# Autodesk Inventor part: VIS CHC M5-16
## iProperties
Created: 2004-11
Part Number: VIS CHC M5-16
Document SubType Name: Modeling
Designer: Bruno
Manufacturer: Standard
Standards Organization: Custom
Author: Bruno
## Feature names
1. Base1
